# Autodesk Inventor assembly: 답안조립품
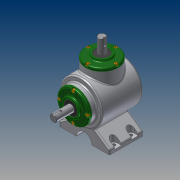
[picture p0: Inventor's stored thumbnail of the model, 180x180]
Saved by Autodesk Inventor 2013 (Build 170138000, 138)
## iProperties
Created: 2017-04
Part Number: 답안조립품
Document SubType Name: Assembly
Designer: Administrator
Author: Administrator
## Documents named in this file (14)
- C:\Users\Administrator\Desktop\470408V1002\답안조립품.iam
- C:\Users\Administrator\Desktop\470408V1002\본체.ipt
- C:\Users\Administrator\Desktop\470408V1002\커버.ipt
- C:\Users\Administrator\Desktop\470408V1002\오일실 17 32 8.ipt
- C:\Users\Administrator\Desktop\470408V1002\볼트 M4.ipt
- C:\Users\Administrator\Desktop\470408V1002\베어링 6203.ipt
- C:\Users\Administrator\Desktop\470408V1002\메인 축.ipt
- 메인 축.ipt
- C:\Users\Administrator\Desktop\470408V1002\서브 축.ipt
- 서브 축.ipt
- C:\Users\Administrator\Desktop\470408V1002\키 5x5.ipt
- C:\Users\Administrator\Desktop\470408V1002\키 4x4.ipt
- C:\Users\Administrator\Desktop\470408V1002\메인 베벨기어.ipt
- C:\Users\Administrator\Desktop\470408V1002\서브 베벨기어.ipt
